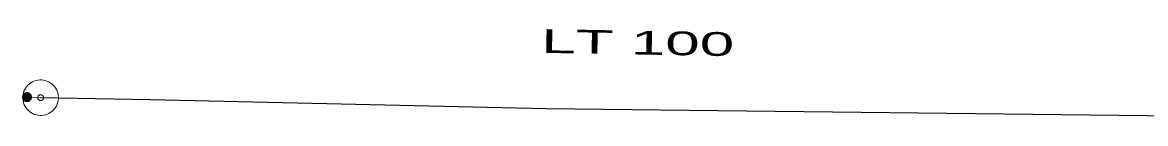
# Model space of a CAD drawing. Extents: x -687468 to -685917, y -974192 to -973456.
# Drawn here: x -686484.78 to -686453.26, y -973579.78 to -973577.32 of the extents above; entities that cross this region are included whole.
import ezdxf
from ezdxf.enums import TextEntityAlignment as Align

# ---------------------------------------------------------------- set-up
doc = ezdxf.new("R2010")
doc.units = 0
doc.header["$LTSCALE"] = 0.27
for name, color, linetype, lineweight in [('1', 7, 'Continuous', 13), ('14', 7, 'Continuous', 25), ('17', 7, 'Continuous', 25), ('47', 7, 'Continuous', 13), ('9', 7, 'Continuous', 13)]:
    doc.layers.add(name, color=color, linetype=linetype, lineweight=lineweight)

msp = doc.modelspace()

# ---------------------------------------------------------------- linework, layer by layer
at = {"layer": '14', "lineweight": 13}
msp.add_line((-686484.267, -973579.246), (-686484.65, -973579.229), dxfattribs=at)
at = {"layer": '17'}
msp.add_lwpolyline([(-686450.807, -973579.784), (-686470.081, -973579.555), (-686481.184, -973579.307), (-686484.267, -973579.246)], dxfattribs=at)
at = {"layer": '47'}
for points in [[(-686483.767, -973579.271), (-686483.767, -973579.219), (-686483.773, -973579.167), (-686483.784, -973579.116), (-686483.8, -973579.066), (-686483.821, -973579.018), (-686483.848, -973578.973), (-686483.879, -973578.931), (-686483.914, -973578.892), (-686483.952, -973578.857), (-686483.995, -973578.826), (-686484.04, -973578.8), (-686484.088, -973578.779), (-686484.137, -973578.763), (-686484.189, -973578.752), (-686484.241, -973578.746), (-686484.293, -973578.746), (-686484.345, -973578.752), (-686484.397, -973578.763), (-686484.446, -973578.779), (-686484.494, -973578.8), (-686484.539, -973578.827), (-686484.582, -973578.858), (-686484.621, -973578.893), (-686484.656, -973578.931), (-686484.686, -973578.974), (-686484.712, -973579.019), (-686484.734, -973579.067), (-686484.749, -973579.116), (-686484.76, -973579.168), (-686484.766, -973579.22), (-686484.766, -973579.272), (-686484.76, -973579.324), (-686484.75, -973579.376), (-686484.733, -973579.425), (-686484.712, -973579.473), (-686484.686, -973579.518), (-686484.655, -973579.561), (-686484.62, -973579.6), (-686484.581, -973579.635), (-686484.538, -973579.665), (-686484.493, -973579.691), (-686484.446, -973579.713), (-686484.396, -973579.728), (-686484.344, -973579.739), (-686484.292, -973579.745), (-686484.24, -973579.745), (-686484.188, -973579.739), (-686484.137, -973579.729), (-686484.087, -973579.712), (-686484.039, -973579.691), (-686483.994, -973579.665), (-686483.952, -973579.634), (-686483.913, -973579.599), (-686483.878, -973579.56), (-686483.847, -973579.517), (-686483.821, -973579.472), (-686483.8, -973579.425), (-686483.784, -973579.375), (-686483.773, -973579.323)], [(-686484.185, -973579.25), (-686484.184, -973579.241), (-686484.186, -973579.233), (-686484.187, -973579.225), (-686484.19, -973579.216), (-686484.193, -973579.208), (-686484.198, -973579.201), (-686484.203, -973579.194), (-686484.208, -973579.187), (-686484.215, -973579.182), (-686484.222, -973579.177), (-686484.23, -973579.172), (-686484.238, -973579.169), (-686484.245, -973579.166), (-686484.253, -973579.164), (-686484.262, -973579.164), (-686484.271, -973579.163), (-686484.279, -973579.165), (-686484.287, -973579.166), (-686484.296, -973579.169), (-686484.304, -973579.172), (-686484.311, -973579.177), (-686484.318, -973579.182), (-686484.325, -973579.187), (-686484.331, -973579.194), (-686484.335, -973579.201), (-686484.34, -973579.209), (-686484.343, -973579.217), (-686484.346, -973579.224), (-686484.348, -973579.232), (-686484.348, -973579.241), (-686484.349, -973579.25), (-686484.347, -973579.258), (-686484.346, -973579.266), (-686484.343, -973579.275), (-686484.34, -973579.283), (-686484.336, -973579.29), (-686484.33, -973579.297), (-686484.325, -973579.304), (-686484.318, -973579.31), (-686484.311, -973579.314), (-686484.303, -973579.319), (-686484.295, -973579.322), (-686484.288, -973579.325), (-686484.28, -973579.327), (-686484.271, -973579.327), (-686484.262, -973579.328), (-686484.254, -973579.326), (-686484.246, -973579.325), (-686484.237, -973579.322), (-686484.229, -973579.319), (-686484.222, -973579.315), (-686484.215, -973579.309), (-686484.208, -973579.304), (-686484.203, -973579.297), (-686484.198, -973579.29), (-686484.193, -973579.282), (-686484.19, -973579.274), (-686484.187, -973579.267), (-686484.185, -973579.259)]]:
    msp.add_lwpolyline(points, close=True, dxfattribs=at)
at = {"layer": '9'}
for points in [[(-686484.524, -973579.229), (-686484.525, -973579.216), (-686484.527, -973579.203), (-686484.53, -973579.19), (-686484.535, -973579.178), (-686484.541, -973579.166), (-686484.548, -973579.155), (-686484.556, -973579.145), (-686484.566, -973579.135), (-686484.576, -973579.127), (-686484.587, -973579.12), (-686484.599, -973579.114), (-686484.611, -973579.109), (-686484.624, -973579.106), (-686484.637, -973579.104), (-686484.65, -973579.103), (-686484.663, -973579.104), (-686484.676, -973579.106), (-686484.689, -973579.109), (-686484.701, -973579.114), (-686484.713, -973579.12), (-686484.724, -973579.127), (-686484.734, -973579.135), (-686484.744, -973579.145), (-686484.752, -973579.155), (-686484.759, -973579.166), (-686484.765, -973579.178), (-686484.77, -973579.19), (-686484.773, -973579.203), (-686484.775, -973579.216), (-686484.776, -973579.229), (-686484.775, -973579.242), (-686484.773, -973579.255), (-686484.77, -973579.268), (-686484.765, -973579.28), (-686484.759, -973579.292), (-686484.752, -973579.303), (-686484.744, -973579.313), (-686484.734, -973579.323), (-686484.724, -973579.331), (-686484.713, -973579.338), (-686484.701, -973579.344), (-686484.689, -973579.349), (-686484.676, -973579.352), (-686484.663, -973579.354), (-686484.65, -973579.355), (-686484.637, -973579.354), (-686484.624, -973579.352), (-686484.611, -973579.349), (-686484.599, -973579.344), (-686484.587, -973579.338), (-686484.576, -973579.331), (-686484.566, -973579.323), (-686484.556, -973579.313), (-686484.548, -973579.303), (-686484.541, -973579.292), (-686484.535, -973579.28), (-686484.53, -973579.268), (-686484.527, -973579.255), (-686484.525, -973579.242)], [(-686484.544, -973579.229), (-686484.544, -973579.218), (-686484.546, -973579.207), (-686484.549, -973579.196), (-686484.553, -973579.186), (-686484.558, -973579.176), (-686484.564, -973579.167), (-686484.571, -973579.158), (-686484.579, -973579.15), (-686484.588, -973579.143), (-686484.597, -973579.137), (-686484.607, -973579.132), (-686484.617, -973579.128), (-686484.628, -973579.125), (-686484.639, -973579.123), (-686484.65, -973579.123), (-686484.661, -973579.123), (-686484.672, -973579.125), (-686484.683, -973579.128), (-686484.693, -973579.132), (-686484.703, -973579.137), (-686484.712, -973579.143), (-686484.721, -973579.15), (-686484.729, -973579.158), (-686484.736, -973579.167), (-686484.742, -973579.176), (-686484.747, -973579.186), (-686484.751, -973579.196), (-686484.754, -973579.207), (-686484.756, -973579.218), (-686484.756, -973579.229), (-686484.756, -973579.24), (-686484.754, -973579.251), (-686484.751, -973579.262), (-686484.747, -973579.272), (-686484.742, -973579.282), (-686484.736, -973579.291), (-686484.729, -973579.3), (-686484.721, -973579.308), (-686484.712, -973579.315), (-686484.703, -973579.321), (-686484.693, -973579.326), (-686484.683, -973579.33), (-686484.672, -973579.333), (-686484.661, -973579.335), (-686484.65, -973579.335), (-686484.639, -973579.335), (-686484.628, -973579.333), (-686484.617, -973579.33), (-686484.607, -973579.326), (-686484.597, -973579.321), (-686484.588, -973579.315), (-686484.579, -973579.308), (-686484.571, -973579.3), (-686484.564, -973579.291), (-686484.558, -973579.282), (-686484.553, -973579.272), (-686484.549, -973579.262), (-686484.546, -973579.251), (-686484.544, -973579.24)], [(-686484.563, -973579.229), (-686484.564, -973579.22), (-686484.565, -973579.211), (-686484.568, -973579.202), (-686484.571, -973579.194), (-686484.575, -973579.186), (-686484.58, -973579.178), (-686484.586, -973579.171), (-686484.592, -973579.165), (-686484.599, -973579.159), (-686484.607, -973579.154), (-686484.615, -973579.15), (-686484.623, -973579.147), (-686484.632, -973579.144), (-686484.641, -973579.143), (-686484.65, -973579.142), (-686484.659, -973579.143), (-686484.668, -973579.144), (-686484.677, -973579.147), (-686484.685, -973579.15), (-686484.693, -973579.154), (-686484.701, -973579.159), (-686484.708, -973579.165), (-686484.714, -973579.171), (-686484.72, -973579.178), (-686484.725, -973579.186), (-686484.729, -973579.194), (-686484.732, -973579.202), (-686484.735, -973579.211), (-686484.736, -973579.22), (-686484.737, -973579.229), (-686484.736, -973579.238), (-686484.735, -973579.247), (-686484.732, -973579.256), (-686484.729, -973579.264), (-686484.725, -973579.272), (-686484.72, -973579.28), (-686484.714, -973579.287), (-686484.708, -973579.293), (-686484.701, -973579.299), (-686484.693, -973579.304), (-686484.685, -973579.308), (-686484.677, -973579.311), (-686484.668, -973579.314), (-686484.659, -973579.315), (-686484.65, -973579.316), (-686484.641, -973579.315), (-686484.632, -973579.314), (-686484.623, -973579.311), (-686484.615, -973579.308), (-686484.607, -973579.304), (-686484.599, -973579.299), (-686484.592, -973579.293), (-686484.586, -973579.287), (-686484.58, -973579.28), (-686484.575, -973579.272), (-686484.571, -973579.264), (-686484.568, -973579.256), (-686484.565, -973579.247), (-686484.564, -973579.238)], [(-686484.583, -973579.229), (-686484.583, -973579.222), (-686484.585, -973579.215), (-686484.586, -973579.208), (-686484.589, -973579.202), (-686484.592, -973579.196), (-686484.596, -973579.19), (-686484.6, -973579.184), (-686484.605, -973579.179), (-686484.611, -973579.175), (-686484.617, -973579.171), (-686484.623, -973579.168), (-686484.629, -973579.165), (-686484.636, -973579.164), (-686484.643, -973579.162), (-686484.65, -973579.162), (-686484.657, -973579.162), (-686484.664, -973579.164), (-686484.671, -973579.165), (-686484.677, -973579.168), (-686484.684, -973579.171), (-686484.689, -973579.175), (-686484.695, -973579.179), (-686484.7, -973579.184), (-686484.704, -973579.19), (-686484.708, -973579.196), (-686484.711, -973579.202), (-686484.714, -973579.208), (-686484.716, -973579.215), (-686484.717, -973579.222), (-686484.717, -973579.229), (-686484.717, -973579.236), (-686484.716, -973579.243), (-686484.714, -973579.25), (-686484.711, -973579.256), (-686484.708, -973579.263), (-686484.704, -973579.268), (-686484.7, -973579.274), (-686484.695, -973579.279), (-686484.689, -973579.283), (-686484.684, -973579.287), (-686484.677, -973579.29), (-686484.671, -973579.293), (-686484.664, -973579.295), (-686484.657, -973579.296), (-686484.65, -973579.296), (-686484.643, -973579.296), (-686484.636, -973579.295), (-686484.629, -973579.293), (-686484.623, -973579.29), (-686484.617, -973579.287), (-686484.611, -973579.283), (-686484.605, -973579.279), (-686484.6, -973579.274), (-686484.596, -973579.268), (-686484.592, -973579.263), (-686484.589, -973579.256), (-686484.586, -973579.25), (-686484.585, -973579.243), (-686484.583, -973579.236)], [(-686484.603, -973579.229), (-686484.603, -973579.224), (-686484.604, -973579.219), (-686484.605, -973579.214), (-686484.607, -973579.21), (-686484.609, -973579.205), (-686484.612, -973579.201), (-686484.615, -973579.198), (-686484.619, -973579.194), (-686484.622, -973579.191), (-686484.626, -973579.188), (-686484.631, -973579.186), (-686484.635, -973579.184), (-686484.64, -973579.183), (-686484.645, -973579.182), (-686484.65, -973579.182), (-686484.655, -973579.182), (-686484.66, -973579.183), (-686484.665, -973579.184), (-686484.669, -973579.186), (-686484.674, -973579.188), (-686484.678, -973579.191), (-686484.682, -973579.194), (-686484.685, -973579.198), (-686484.688, -973579.201), (-686484.691, -973579.205), (-686484.693, -973579.21), (-686484.695, -973579.214), (-686484.696, -973579.219), (-686484.697, -973579.224), (-686484.697, -973579.229), (-686484.697, -973579.234), (-686484.696, -973579.239), (-686484.695, -973579.244), (-686484.693, -973579.248), (-686484.691, -973579.253), (-686484.688, -973579.257), (-686484.685, -973579.261), (-686484.682, -973579.264), (-686484.678, -973579.267), (-686484.674, -973579.27), (-686484.669, -973579.272), (-686484.665, -973579.274), (-686484.66, -973579.275), (-686484.655, -973579.276), (-686484.65, -973579.276), (-686484.645, -973579.276), (-686484.64, -973579.275), (-686484.635, -973579.274), (-686484.631, -973579.272), (-686484.626, -973579.27), (-686484.622, -973579.267), (-686484.619, -973579.264), (-686484.615, -973579.261), (-686484.612, -973579.257), (-686484.609, -973579.253), (-686484.607, -973579.248), (-686484.605, -973579.244), (-686484.604, -973579.239), (-686484.603, -973579.234)], [(-686484.623, -973579.229), (-686484.623, -973579.226), (-686484.623, -973579.223), (-686484.624, -973579.221), (-686484.625, -973579.218), (-686484.626, -973579.215), (-686484.628, -973579.213), (-686484.63, -973579.211), (-686484.632, -973579.209), (-686484.634, -973579.207), (-686484.636, -973579.205), (-686484.639, -973579.204), (-686484.642, -973579.203), (-686484.644, -973579.202), (-686484.647, -973579.202), (-686484.65, -973579.202), (-686484.653, -973579.202), (-686484.656, -973579.202), (-686484.659, -973579.203), (-686484.661, -973579.204), (-686484.664, -973579.205), (-686484.666, -973579.207), (-686484.669, -973579.209), (-686484.671, -973579.211), (-686484.672, -973579.213), (-686484.674, -973579.215), (-686484.675, -973579.218), (-686484.676, -973579.221), (-686484.677, -973579.223), (-686484.677, -973579.226), (-686484.678, -973579.229), (-686484.677, -973579.232), (-686484.677, -973579.235), (-686484.676, -973579.238), (-686484.675, -973579.24), (-686484.674, -973579.243), (-686484.672, -973579.245), (-686484.671, -973579.248), (-686484.669, -973579.25), (-686484.666, -973579.251), (-686484.664, -973579.253), (-686484.661, -973579.254), (-686484.659, -973579.255), (-686484.656, -973579.256), (-686484.653, -973579.256), (-686484.65, -973579.257), (-686484.647, -973579.256), (-686484.644, -973579.256), (-686484.642, -973579.255), (-686484.639, -973579.254), (-686484.636, -973579.253), (-686484.634, -973579.251), (-686484.632, -973579.25), (-686484.63, -973579.248), (-686484.628, -973579.245), (-686484.626, -973579.243), (-686484.625, -973579.24), (-686484.624, -973579.238), (-686484.623, -973579.235), (-686484.623, -973579.232)], [(-686484.642, -973579.229), (-686484.642, -973579.228), (-686484.642, -973579.227), (-686484.643, -973579.227), (-686484.643, -973579.226), (-686484.643, -973579.225), (-686484.644, -973579.224), (-686484.644, -973579.224), (-686484.645, -973579.223), (-686484.645, -973579.223), (-686484.646, -973579.222), (-686484.647, -973579.222), (-686484.648, -973579.222), (-686484.648, -973579.221), (-686484.649, -973579.221), (-686484.65, -973579.221), (-686484.651, -973579.221), (-686484.652, -973579.221), (-686484.652, -973579.222), (-686484.653, -973579.222), (-686484.654, -973579.222), (-686484.655, -973579.223), (-686484.655, -973579.223), (-686484.656, -973579.224), (-686484.656, -973579.224), (-686484.657, -973579.225), (-686484.657, -973579.226), (-686484.658, -973579.227), (-686484.658, -973579.227), (-686484.658, -973579.228), (-686484.658, -973579.229), (-686484.658, -973579.23), (-686484.658, -973579.231), (-686484.658, -973579.231), (-686484.657, -973579.232), (-686484.657, -973579.233), (-686484.656, -973579.234), (-686484.656, -973579.234), (-686484.655, -973579.235), (-686484.655, -973579.235), (-686484.654, -973579.236), (-686484.653, -973579.236), (-686484.652, -973579.237), (-686484.652, -973579.237), (-686484.651, -973579.237), (-686484.65, -973579.237), (-686484.649, -973579.237), (-686484.648, -973579.237), (-686484.648, -973579.237), (-686484.647, -973579.236), (-686484.646, -973579.236), (-686484.645, -973579.235), (-686484.645, -973579.235), (-686484.644, -973579.234), (-686484.644, -973579.234), (-686484.643, -973579.233), (-686484.643, -973579.232), (-686484.643, -973579.231), (-686484.642, -973579.231), (-686484.642, -973579.23)]]:
    msp.add_lwpolyline(points, close=True, dxfattribs=at)

# ---------------------------------------------------------------- texts
at = {"layer": '1', "width": 1.95}
msp.add_text('LT 100', height=0.6667, rotation=359, dxfattribs=at).set_placement((-686467.518, -973578.034), align=Align.CENTER)

doc.saveas('drawing.dxf')
